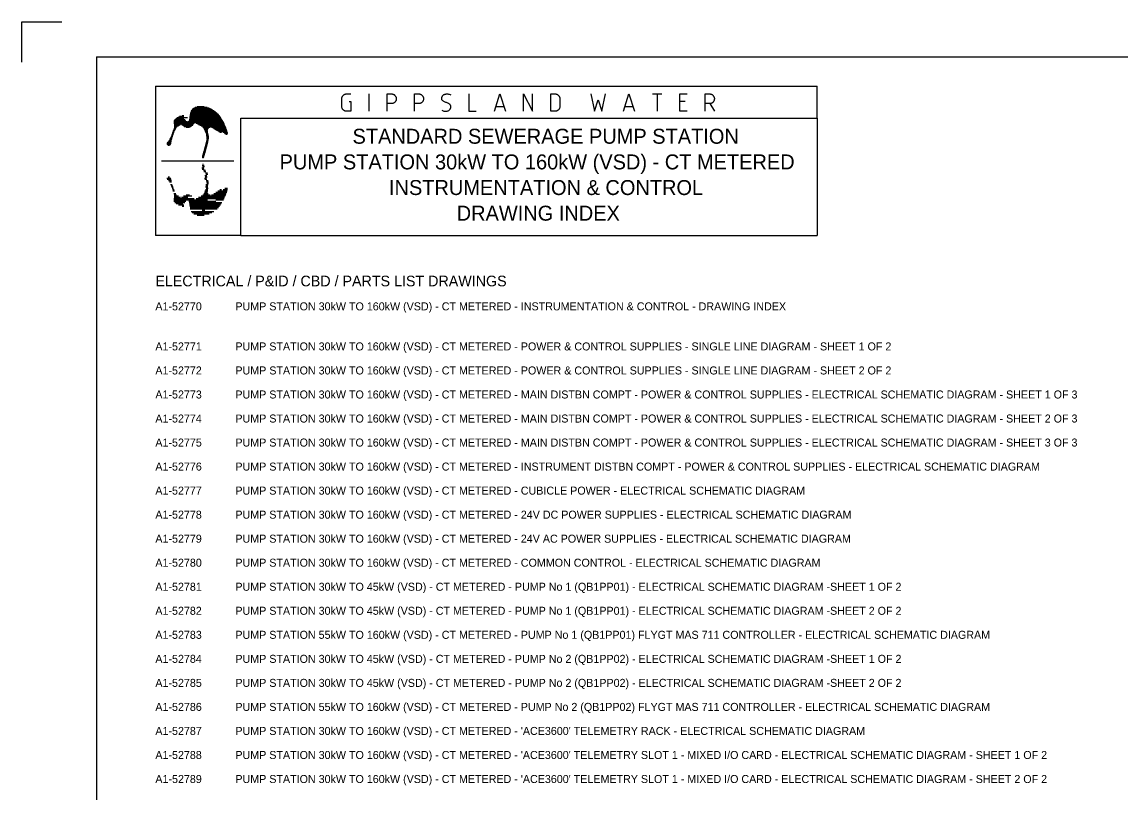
# Model space of a CAD drawing. Extents: x 0 to 841, y 0 to 594.
# Drawn here: x 0 to 411.6, y 305.6 to 594 of the extents above; entities that cross this region are included whole.
import ezdxf

# ---------------------------------------------------------------- set-up
doc = ezdxf.new("R2010")
doc.units = 0
for name, color, linetype in [('A1BORDER', 7, 'Continuous'), ('Level 1', 7, 'Continuous'), ('Level 10', 7, 'Continuous')]:
    doc.layers.add(name, color=color, linetype=linetype)

msp = doc.modelspace()

# ---------------------------------------------------------------- linework, layer by layer
at = {"layer": 'A1BORDER'}
for p, q in [((0, 594), (15, 594)), ((0, 579), (0, 594)), ((28, 581), (829, 581)), ((28, 581), (28, 15))]:
    msp.add_line(p, q, dxfattribs=at)
at = {"layer": 'Level 1'}
for p in [(298, 558), (82, 514)]:
    msp.add_line(p, (298, 514), dxfattribs=at)
at = {"layer": 'Level 10'}
for p, q in [((50, 570), (298, 570)), ((50, 570), (50, 514)), ((298, 558), (298, 570)), ((63.092, 559.904), (73.16, 559.904)), ((63.152, 560.144), (72.896, 560.144)), ((63.236, 560.384), (72.62, 560.384)), ((63.344, 560.624), (72.308, 560.624)), ((63.476, 560.864), (71.972, 560.864)), ((63.644, 561.104), (71.6, 561.104)), ((63.836, 561.344), (71.168, 561.344)), ((64.088, 561.584), (70.688, 561.584)), ((64.424, 561.824), (70.112, 561.824)), ((64.868, 562.064), (69.38, 562.064)), ((65.612, 562.304), (68.24, 562.304)), ((56.876, 556.544), (75.5, 556.544)), ((56.888, 556.304), (75.62, 556.304)), ((56.9, 556.784), (61.748, 556.784)), ((56.948, 556.064), (64.496, 556.064)), ((56.972, 557.024), (61.46, 557.024)), ((56.996, 555.824), (64.34, 555.824)), ((57.08, 557.264), (61.244, 557.264)), ((57.248, 557.504), (60.992, 557.504)), ((57.512, 557.744), (60.68, 557.744)), ((57.848, 557.984), (60.284, 557.984)), ((58.22, 558.224), (62.108, 558.224)), ((58.616, 558.464), (60.668, 558.464)), ((59.048, 558.704), (60.032, 558.704)), ((60.044, 558.944), (60.632, 558.944)), ((62.228, 556.784), (75.368, 556.784)), ((62.504, 557.024), (75.236, 557.024)), ((62.648, 557.264), (75.104, 557.264)), ((62.732, 557.504), (74.96, 557.504)), ((62.756, 557.744), (74.816, 557.744)), ((62.792, 557.984), (74.684, 557.984)), ((62.828, 558.224), (74.528, 558.224)), ((62.852, 558.464), (74.372, 558.464)), ((62.9, 558.704), (74.204, 558.704)), ((62.936, 558.944), (74.024, 558.944)), ((62.972, 559.184), (73.832, 559.184)), ((63.02, 559.424), (73.628, 559.424)), ((63.056, 559.664), (73.4, 559.664)), ((65.264, 556.064), (75.74, 556.064)), ((65.744, 555.824), (75.86, 555.824)), ((82, 558), (298, 558)), ((82, 514), (82, 558)), ((56.072, 551.744), (56.66, 551.744)), ((56.156, 551.984), (56.744, 551.984)), ((56.252, 552.224), (56.828, 552.224)), ((56.336, 552.464), (56.912, 552.464)), ((56.42, 552.704), (56.996, 552.704)), ((56.516, 552.944), (57.08, 552.944)), ((56.6, 553.184), (57.2, 553.184)), ((56.684, 553.424), (57.32, 553.424)), ((56.78, 553.664), (57.44, 553.664)), ((56.864, 553.904), (57.56, 553.904)), ((56.948, 554.144), (57.68, 554.144)), ((57.008, 554.384), (57.8, 554.384)), ((57.02, 555.572), (59.456, 555.572)), ((57.044, 555.344), (59.084, 555.344)), ((57.044, 554.624), (57.92, 554.624)), ((57.056, 555.104), (58.676, 555.104)), ((57.056, 554.864), (58.196, 554.864)), ((59.768, 555.572), (64.196, 555.572)), ((60.188, 555.344), (64.004, 555.344)), ((60.512, 555.104), (63.704, 555.104)), ((60.86, 554.864), (63.332, 554.864)), ((61.544, 554.624), (62.804, 554.624)), ((66.176, 555.572), (75.968, 555.572)), ((66.644, 555.344), (76.076, 555.344)), ((67.232, 555.104), (76.184, 555.104)), ((67.712, 554.864), (76.28, 554.864)), ((67.856, 554.624), (70.58, 554.624)), ((67.988, 554.384), (70.052, 554.384)), ((68.12, 554.144), (69.824, 554.144)), ((68.24, 553.904), (69.68, 553.904)), ((68.372, 553.664), (69.596, 553.664)), ((68.492, 553.424), (69.572, 553.424)), ((68.6, 553.184), (69.608, 553.184)), ((68.72, 552.944), (69.656, 552.944)), ((68.828, 552.704), (69.692, 552.704)), ((68.936, 552.464), (69.728, 552.464)), ((68.996, 552.224), (69.776, 552.224)), ((69.032, 551.984), (69.836, 551.984)), ((69.068, 551.744), (69.884, 551.744)), ((71.084, 554.624), (76.388, 554.624)), ((71.6, 554.384), (76.484, 554.384)), ((71.972, 554.144), (76.568, 554.144)), ((72.344, 553.904), (76.664, 553.904)), ((72.716, 553.664), (76.748, 553.664)), ((73.088, 553.424), (76.82, 553.424)), ((73.46, 553.184), (76.904, 553.184)), ((73.832, 552.944), (74.888, 552.944)), ((74.204, 552.704), (74.816, 552.704)), ((74.612, 552.464), (74.648, 552.464)), ((75.092, 552.944), (76.976, 552.944)), ((75.428, 552.704), (77.048, 552.704)), ((75.764, 552.464), (77.108, 552.464)), ((76.1, 552.224), (77.096, 552.224)), ((76.424, 551.984), (76.964, 551.984)), ((54.344, 548.384), (55.856, 548.384)), ((54.356, 548.624), (55.916, 548.624)), ((54.464, 548.144), (55.676, 548.144)), ((54.476, 548.864), (55.94, 548.864)), ((54.68, 549.104), (55.964, 549.104)), ((54.836, 547.904), (55.316, 547.904)), ((54.92, 549.344), (56, 549.344)), ((55.1, 549.572), (56.048, 549.572)), ((55.244, 549.824), (56.108, 549.824)), ((55.352, 550.064), (56.18, 550.064)), ((55.46, 550.304), (56.24, 550.304)), ((55.568, 550.544), (56.3, 550.544)), ((55.676, 550.784), (56.36, 550.784)), ((55.784, 551.012), (56.42, 551.012)), ((55.892, 551.264), (56.492, 551.264)), ((55.988, 551.504), (56.576, 551.504)), ((68.564, 547.424), (69.32, 547.424)), ((68.624, 547.664), (69.38, 547.664)), ((68.684, 547.904), (69.44, 547.904)), ((68.756, 548.144), (69.512, 548.144)), ((68.816, 548.384), (69.572, 548.384)), ((68.888, 548.624), (69.644, 548.624)), ((68.948, 548.864), (69.692, 548.864)), ((69.02, 549.104), (69.74, 549.104)), ((69.08, 549.344), (69.788, 549.344)), ((69.092, 551.504), (69.944, 551.504)), ((69.128, 551.264), (70.004, 551.264)), ((69.14, 549.572), (69.836, 549.572)), ((69.164, 551.012), (70.052, 551.012)), ((69.188, 549.824), (69.884, 549.824)), ((69.2, 550.784), (70.028, 550.784)), ((69.224, 550.544), (70.004, 550.544)), ((69.236, 550.064), (69.932, 550.064)), ((69.26, 550.304), (69.968, 550.304)), ((67.556, 543.584), (68.276, 543.584)), ((67.568, 543.344), (68.204, 543.344)), ((67.58, 543.824), (68.336, 543.824)), ((67.652, 544.064), (68.408, 544.064)), ((67.712, 544.304), (68.468, 544.304)), ((67.784, 544.544), (68.528, 544.544)), ((67.844, 544.784), (68.6, 544.784)), ((67.904, 545.024), (68.66, 545.024)), ((67.976, 545.264), (68.732, 545.264)), ((68.036, 545.504), (68.792, 545.504)), ((68.108, 545.744), (68.864, 545.744)), ((68.168, 545.984), (68.924, 545.984)), ((68.24, 546.224), (68.984, 546.224)), ((68.3, 546.464), (69.056, 546.464)), ((68.36, 546.704), (69.116, 546.704)), ((68.432, 546.944), (69.188, 546.944)), ((68.492, 547.184), (69.248, 547.184)), ((52.316, 541.976), (79.364, 541.976)), ((67.448, 539.408), (68.204, 539.408)), ((67.556, 540.368), (68.276, 540.368)), ((67.652, 539.888), (68.408, 539.888)), ((67.748, 543.104), (67.88, 543.104)), ((67.748, 540.848), (67.88, 540.848)), ((54.344, 535.568), (55.856, 535.568)), ((54.476, 535.088), (55.94, 535.088)), ((54.836, 536.048), (55.316, 536.048)), ((67.58, 538.928), (68.336, 538.928)), ((68.036, 538.448), (68.792, 538.448)), ((68.168, 537.968), (68.924, 537.968)), ((68.408, 535.568), (69.164, 535.568)), ((68.54, 535.088), (69.284, 535.088)), ((68.564, 536.528), (69.32, 536.528)), ((68.684, 536.048), (69.44, 536.048)), ((68.792, 537.488), (69.548, 537.488)), ((68.924, 537.008), (69.68, 537.008)), ((54.92, 534.608), (56, 534.608)), ((55.244, 534.128), (56.108, 534.128)), ((55.676, 533.168), (56.36, 533.168)), ((55.892, 532.688), (56.492, 532.688)), ((56.072, 532.208), (56.66, 532.208)), ((56.252, 531.728), (56.828, 531.728)), ((56.42, 531.248), (56.996, 531.248)), ((68.792, 532.208), (69.62, 532.208)), ((68.828, 531.248), (69.692, 531.248)), ((68.864, 532.688), (69.728, 532.688)), ((68.924, 533.168), (69.752, 533.168)), ((68.996, 531.728), (69.776, 531.728)), ((69.08, 534.608), (69.788, 534.608)), ((69.188, 534.128), (69.884, 534.128)), ((69.26, 533.648), (69.968, 533.648)), ((74.204, 531.248), (74.816, 531.248)), ((75.428, 531.248), (77.048, 531.248)), ((76.1, 531.728), (77.096, 531.728)), ((56.6, 530.768), (57.2, 530.768)), ((56.876, 527.408), (69.524, 527.408)), ((56.948, 529.808), (57.68, 529.808)), ((56.948, 527.888), (64.496, 527.888)), ((56.972, 526.928), (61.46, 526.928)), ((57.02, 528.38), (59.456, 528.38)), ((57.044, 529.328), (57.92, 529.328)), ((57.056, 528.848), (58.676, 528.848)), ((59.768, 528.38), (62.216, 528.38)), ((60.512, 528.848), (63.704, 528.848)), ((61.544, 529.328), (62.804, 529.328)), ((62.504, 526.928), (72.668, 526.928)), ((65.264, 527.888), (75.74, 527.888)), ((66.176, 528.38), (75.968, 528.38)), ((67.232, 528.848), (76.184, 528.848)), ((67.856, 529.328), (70.58, 529.328)), ((68.12, 529.808), (69.824, 529.808)), ((68.372, 530.288), (69.596, 530.288)), ((68.6, 530.768), (69.608, 530.768)), ((71.084, 529.328), (76.388, 529.328)), ((71.972, 529.808), (76.568, 529.808)), ((72.716, 530.288), (76.748, 530.288)), ((72.728, 527.408), (75.5, 527.408)), ((73.46, 530.768), (76.904, 530.768)), ((57.248, 526.448), (60.992, 526.448)), ((57.848, 525.968), (60.284, 525.968)), ((58.616, 525.488), (60.668, 525.488)), ((60.044, 525.008), (60.632, 525.008)), ((62.732, 526.448), (74.96, 526.448)), ((62.792, 525.968), (74.684, 525.968)), ((62.852, 525.488), (74.372, 525.488)), ((62.936, 525.008), (74.024, 525.008)), ((63.02, 524.528), (73.628, 524.528)), ((63.092, 524.048), (73.16, 524.048)), ((63.476, 523.088), (71.972, 523.088)), ((67.484, 523.568), (68.528, 523.568)), ((63.836, 522.608), (71.168, 522.608)), ((64.424, 522.128), (70.112, 522.128)), ((65.612, 521.648), (68.24, 521.648)), ((82, 514), (50, 514))]:
    msp.add_line(p, q, dxfattribs=at)
for points in [[(122.588, 564.18), (123.272, 564.18), (123.272, 560.592), (121.568, 560.592), (121.412, 560.592), (121.268, 560.616), (121.136, 560.652), (120.98, 560.7), (120.848, 560.76), (120.716, 560.832), (120.584, 560.916), (120.476, 561.012), (120.368, 561.12), (120.26, 561.24), (120.176, 561.36), (120.092, 561.492), (120.02, 561.624), (119.972, 561.768), (119.924, 561.924), (119.888, 562.068), (119.864, 562.224), (119.864, 562.392), (119.864, 565.26), (119.864, 565.416), (119.888, 565.572), (119.924, 565.716), (119.972, 565.872), (120.02, 566.004), (120.092, 566.148), (120.176, 566.28), (120.26, 566.4), (120.368, 566.52), (120.476, 566.628), (120.584, 566.724), (120.716, 566.808), (120.848, 566.88), (120.98, 566.94), (121.136, 566.988), (121.268, 567.024), (121.412, 567.048), (121.568, 567.048), (123.272, 567.048)], [(130.088, 560.592), (130.088, 567.048)], [(136.904, 560.592), (136.904, 567.048), (138.608, 567.048), (138.752, 567.048), (138.896, 567.024), (139.04, 566.988), (139.184, 566.94), (139.316, 566.88), (139.448, 566.808), (139.58, 566.724), (139.688, 566.628), (139.808, 566.52), (139.904, 566.4), (139.988, 566.28), (140.072, 566.148), (140.144, 566.004), (140.204, 565.872), (140.252, 565.716), (140.276, 565.572), (140.3, 565.416), (140.312, 565.26), (140.3, 565.092), (140.276, 564.936), (140.252, 564.792), (140.204, 564.636), (140.144, 564.504), (140.072, 564.36), (139.988, 564.228), (139.904, 564.108), (139.808, 563.988), (139.688, 563.88), (139.58, 563.784), (139.448, 563.7), (139.316, 563.628), (139.184, 563.568), (139.04, 563.52), (138.896, 563.484), (138.752, 563.46), (138.608, 563.46), (136.904, 563.46)], [(147.116, 560.592), (147.116, 567.048), (148.82, 567.048), (148.964, 567.048), (149.108, 567.024), (149.252, 566.988), (149.396, 566.94), (149.528, 566.88), (149.66, 566.808), (149.792, 566.724), (149.912, 566.628), (150.02, 566.52), (150.116, 566.4), (150.212, 566.28), (150.284, 566.148), (150.356, 566.004), (150.416, 565.872), (150.464, 565.716), (150.5, 565.572), (150.512, 565.416), (150.524, 565.26), (150.512, 565.092), (150.5, 564.936), (150.464, 564.792), (150.416, 564.636), (150.356, 564.504), (150.284, 564.36), (150.212, 564.228), (150.116, 564.108), (150.02, 563.988), (149.912, 563.88), (149.792, 563.784), (149.66, 563.7), (149.528, 563.628), (149.396, 563.568), (149.252, 563.52), (149.108, 563.484), (148.964, 563.46), (148.82, 563.46), (147.116, 563.46)], [(157.34, 560.952), (157.604, 560.832), (157.88, 560.724), (158.144, 560.652), (158.432, 560.604), (158.72, 560.592), (159.008, 560.592), (159.044, 560.592), (159.236, 560.616), (159.416, 560.652), (159.596, 560.712), (159.776, 560.784), (159.944, 560.88), (160.064, 560.952), (160.172, 561.036), (160.28, 561.132), (160.376, 561.228), (160.46, 561.336), (160.532, 561.456), (160.604, 561.588), (160.664, 561.708), (160.7, 561.852), (160.736, 561.984), (160.748, 562.032), (160.76, 562.128), (160.76, 562.224), (160.76, 562.332), (160.748, 562.428), (160.724, 562.524), (160.7, 562.632), (160.664, 562.716), (160.616, 562.812), (160.568, 562.908), (160.508, 562.98), (160.448, 563.052), (160.412, 563.1), (160.22, 563.268), (160.028, 563.412), (159.824, 563.532), (159.608, 563.64), (159.38, 563.736), (159.14, 563.796), (159.044, 563.82), (158.816, 563.88), (158.588, 563.952), (158.36, 564.048), (158.144, 564.168), (157.952, 564.312), (157.76, 564.468), (157.676, 564.54), (157.604, 564.612), (157.544, 564.684), (157.496, 564.768), (157.436, 564.852), (157.4, 564.948), (157.364, 565.044), (157.352, 565.14), (157.328, 565.248), (157.316, 565.344), (157.316, 565.452), (157.328, 565.548), (157.34, 565.62), (157.364, 565.752), (157.412, 565.896), (157.46, 566.028), (157.532, 566.148), (157.604, 566.268), (157.688, 566.388), (157.784, 566.484), (157.88, 566.58), (157.988, 566.676), (158.024, 566.688), (158.18, 566.796), (158.36, 566.88), (158.528, 566.94), (158.72, 567), (158.9, 567.024), (159.044, 567.048), (159.332, 567.06), (159.62, 567.036), (159.896, 566.988), (160.184, 566.916), (160.448, 566.82), (160.724, 566.7)], [(167.552, 567.048), (167.552, 560.592), (170.276, 560.592)], [(177.092, 560.592), (179.132, 567.048), (181.184, 560.592)], [(187.988, 560.592), (187.988, 567.048), (191.396, 560.592), (191.396, 567.048)], [(198.224, 560.592), (198.224, 567.048), (199.928, 567.048), (200.072, 567.048), (200.216, 567.024), (200.36, 566.988), (200.504, 566.94), (200.636, 566.88), (200.768, 566.808), (200.9, 566.724), (201.008, 566.628), (201.128, 566.52), (201.224, 566.4), (201.308, 566.28), (201.392, 566.148), (201.464, 566.004), (201.524, 565.872), (201.572, 565.716), (201.596, 565.572), (201.62, 565.416), (201.632, 565.26), (201.632, 562.392), (201.62, 562.224), (201.596, 562.068), (201.572, 561.924), (201.524, 561.768), (201.464, 561.624), (201.392, 561.492), (201.308, 561.36), (201.224, 561.24), (201.128, 561.12), (201.008, 561.012), (200.9, 560.916), (200.768, 560.832), (200.636, 560.76), (200.504, 560.7), (200.36, 560.652), (200.216, 560.616), (200.072, 560.592), (199.928, 560.592), (198.224, 560.592)], [(213.212, 567.048), (214.568, 560.592), (215.936, 564.9), (217.292, 560.592), (218.66, 567.048)], [(225.464, 560.592), (227.504, 567.048), (229.556, 560.592)], [(236.372, 567.048), (239.78, 567.048)], [(238.076, 567.048), (238.076, 560.592)], [(249.308, 560.592), (246.584, 560.592), (246.584, 567.048), (249.308, 567.048)], [(248.636, 564.18), (246.584, 564.18)], [(256.136, 560.592), (256.136, 567.048), (257.84, 567.048), (257.984, 567.048), (258.128, 567.024), (258.272, 566.988), (258.416, 566.94), (258.548, 566.88), (258.68, 566.808), (258.812, 566.724), (258.92, 566.628), (259.04, 566.52), (259.136, 566.4), (259.22, 566.28), (259.304, 566.148), (259.376, 566.004), (259.436, 565.872), (259.472, 565.716), (259.508, 565.572), (259.532, 565.416), (259.532, 565.26), (259.532, 565.092), (259.508, 564.936), (259.472, 564.792), (259.436, 564.636), (259.376, 564.504), (259.304, 564.36), (259.22, 564.228), (259.136, 564.108), (259.04, 563.988), (258.92, 563.88), (258.812, 563.784), (258.68, 563.7), (258.548, 563.628), (258.416, 563.568), (258.272, 563.52), (258.128, 563.484), (257.984, 563.46), (257.84, 563.46), (256.136, 563.46)], [(177.776, 562.392), (180.5, 562.392)], [(226.148, 562.392), (228.872, 562.392)], [(257.84, 563.46), (259.532, 560.592)]]:
    msp.add_lwpolyline(points, dxfattribs=at)

# ---------------------------------------------------------------- texts
at = {"layer": 'Level 1'}
for s, height, p in [('STANDARD SEWERAGE PUMP STATION', 5.60002, (123.899, 548.4)), ('PUMP STATION 30kW TO 160kW (VSD) - CT METERED', 5.60002, (96.566, 538.8)), ('INSTRUMENTATION & CONTROL', 5.60002, (137.565, 529.2)), ('DRAWING INDEX', 5.60002, (162.946, 519.6)), ('ELECTRICAL / P&ID / CBD / PARTS LIST DRAWINGS', 4, (50, 495)), ('A1-52770', 3, (50, 486)), ('PUMP STATION 30kW TO 160kW (VSD) - CT METERED - INSTRUMENTATION & CONTROL - DRAWING INDEX', 3, (80, 486)), ('A1-52771', 3, (50, 471)), ('PUMP STATION 30kW TO 160kW (VSD) - CT METERED - POWER & CONTROL SUPPLIES - SINGLE LINE DIAGRAM - SHEET 1 OF 2', 3, (80, 471)), ('PUMP STATION 30kW TO 160kW (VSD) - CT METERED - POWER & CONTROL SUPPLIES - SINGLE LINE DIAGRAM - SHEET 2 OF 2', 3, (80, 462)), ('A1-52772', 3, (50, 462)), ('A1-52773', 3, (50, 453)), ('PUMP STATION 30kW TO 160kW (VSD) - CT METERED - MAIN DISTBN COMPT - POWER & CONTROL SUPPLIES - ELECTRICAL SCHEMATIC DIAGRAM - SHEET 1 OF 3', 3, (80, 453)), ('A1-52774', 3, (50, 444)), ('PUMP STATION 30kW TO 160kW (VSD) - CT METERED - MAIN DISTBN COMPT - POWER & CONTROL SUPPLIES - ELECTRICAL SCHEMATIC DIAGRAM - SHEET 2 OF 3', 3, (80, 444)), ('A1-52775', 3, (50, 435)), ('PUMP STATION 30kW TO 160kW (VSD) - CT METERED - MAIN DISTBN COMPT - POWER & CONTROL SUPPLIES - ELECTRICAL SCHEMATIC DIAGRAM - SHEET 3 OF 3', 3, (80, 435)), ('A1-52776', 3, (50, 426)), ('PUMP STATION 30kW TO 160kW (VSD) - CT METERED - INSTRUMENT DISTBN COMPT - POWER & CONTROL SUPPLIES - ELECTRICAL SCHEMATIC DIAGRAM', 3, (80, 426)), ('A1-52777', 3, (50, 417)), ('PUMP STATION 30kW TO 160kW (VSD) - CT METERED - CUBICLE POWER - ELECTRICAL SCHEMATIC DIAGRAM', 3, (80, 417)), ('A1-52778', 3, (50, 408)), ('PUMP STATION 30kW TO 160kW (VSD) - CT METERED - 24V DC POWER SUPPLIES - ELECTRICAL SCHEMATIC DIAGRAM', 3, (80, 408)), ('A1-52779', 3, (50, 399)), ('PUMP STATION 30kW TO 160kW (VSD) - CT METERED - 24V AC POWER SUPPLIES - ELECTRICAL SCHEMATIC DIAGRAM', 3, (80, 399)), ('A1-52780', 3, (50, 390)), ('PUMP STATION 30kW TO 160kW (VSD) - CT METERED - COMMON CONTROL - ELECTRICAL SCHEMATIC DIAGRAM', 3, (80, 390)), ('A1-52781', 3, (50, 381)), ('PUMP STATION 30kW TO 45kW (VSD) - CT METERED - PUMP No 1 (QB1PP01) - ELECTRICAL SCHEMATIC DIAGRAM -SHEET 1 OF 2', 3, (80, 381)), ('A1-52782', 3, (50, 372)), ('PUMP STATION 30kW TO 45kW (VSD) - CT METERED - PUMP No 1 (QB1PP01) - ELECTRICAL SCHEMATIC DIAGRAM -SHEET 2 OF 2', 3, (80, 372)), ('A1-52783', 3, (50, 363)), ('PUMP STATION 55kW TO 160kW (VSD) - CT METERED - PUMP No 1 (QB1PP01) FLYGT MAS 711 CONTROLLER - ELECTRICAL SCHEMATIC DIAGRAM', 3, (80, 363)), ('A1-52784', 3, (50, 354)), ('PUMP STATION 30kW TO 45kW (VSD) - CT METERED - PUMP No 2 (QB1PP02) - ELECTRICAL SCHEMATIC DIAGRAM -SHEET 1 OF 2', 3, (80, 354)), ('A1-52785', 3, (50, 345)), ('PUMP STATION 30kW TO 45kW (VSD) - CT METERED - PUMP No 2 (QB1PP02) - ELECTRICAL SCHEMATIC DIAGRAM -SHEET 2 OF 2', 3, (80, 345)), ('A1-52786', 3, (50, 336)), ('PUMP STATION 55kW TO 160kW (VSD) - CT METERED - PUMP No 2 (QB1PP02) FLYGT MAS 711 CONTROLLER - ELECTRICAL SCHEMATIC DIAGRAM', 3, (80, 336)), ('A1-52787', 3, (50, 327)), ("PUMP STATION 30kW TO 160kW (VSD) - CT METERED - 'ACE3600' TELEMETRY RACK - ELECTRICAL SCHEMATIC DIAGRAM", 3, (80, 327)), ('A1-52788', 3, (50, 318)), ("PUMP STATION 30kW TO 160kW (VSD) - CT METERED - 'ACE3600' TELEMETRY SLOT 1 - MIXED I/O CARD - ELECTRICAL SCHEMATIC DIAGRAM - SHEET 1 OF 2", 3, (80, 318)), ('A1-52789', 3, (50, 309)), ("PUMP STATION 30kW TO 160kW (VSD) - CT METERED - 'ACE3600' TELEMETRY SLOT 1 - MIXED I/O CARD - ELECTRICAL SCHEMATIC DIAGRAM - SHEET 2 OF 2", 3, (80, 309))]:
    msp.add_text(s, height=height, dxfattribs=at).set_placement(p)

doc.saveas('drawing.dxf')
